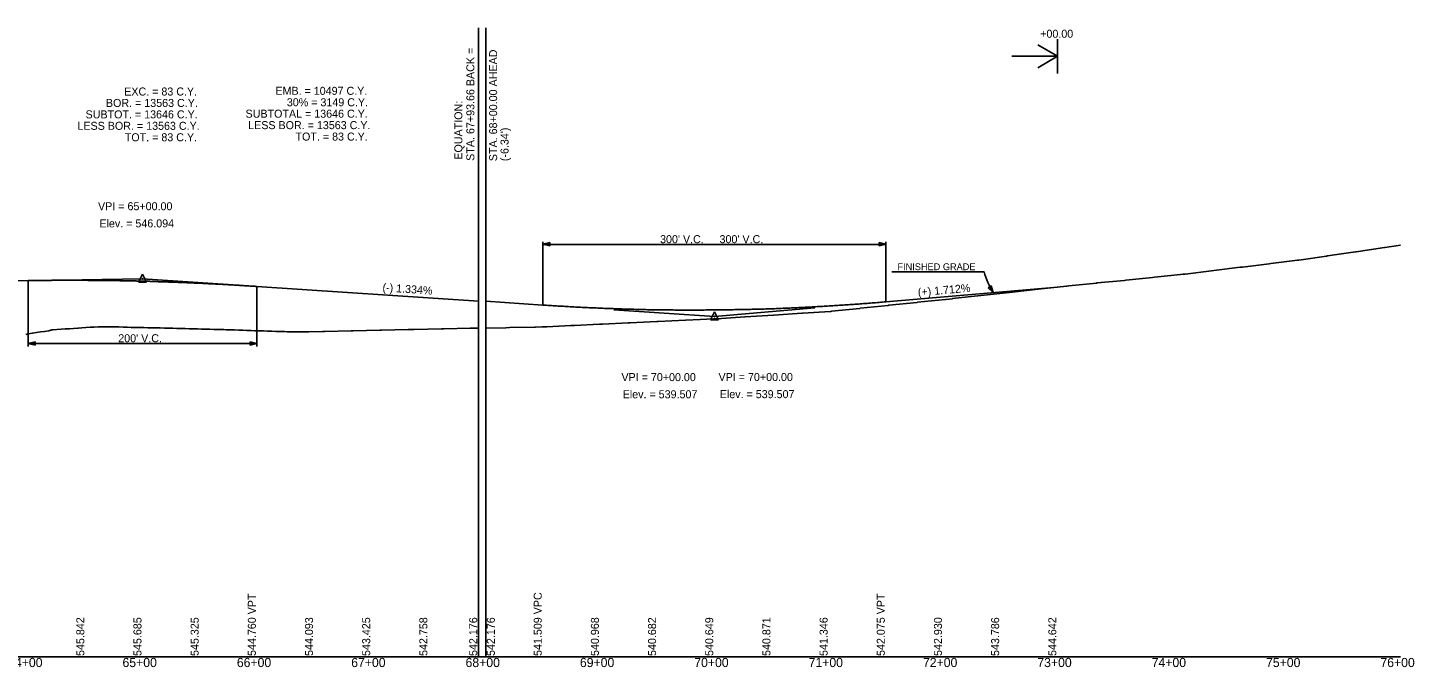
# Model space of a CAD drawing. Extents: x 1961504 to 1964196, y 1107046 to 1115093.
# Drawn here: x 1962983 to 1964196, y 1107083 to 1107643 of the extents above; entities that cross this region are included whole.
import ezdxf

# ---------------------------------------------------------------- set-up
doc = ezdxf.new("R2010")
doc.units = 0
for name, color, linetype in [('Level 40', 7, 'Continuous'), ('Level 41', 7, 'Continuous'), ('Level 42', 7, 'Continuous'), ('Level 43', 7, 'Continuous'), ('Level 45', 7, 'Continuous'), ('Level 58', 7, 'Continuous'), ('Level 63', 7, 'Continuous')]:
    doc.layers.add(name, color=color, linetype=linetype)

msp = doc.modelspace()

# ---------------------------------------------------------------- linework, layer by layer
at = {"layer": 'Level 40'}
for points in [[(1963383.7, 1107379.9), (1963401.3, 1107380.3), (1963404.6, 1107380.4), (1963426.3, 1107380.8), (1963427.3, 1107380.9), (1963433.2, 1107381), (1963437.1, 1107381.2), (1963458.2, 1107382.2), (1963461.5, 1107382.3), (1963483.2, 1107383.4), (1963485.8, 1107383.5), (1963508.3, 1107384.5), (1963510.1, 1107384.6), (1963533.3, 1107385.7), (1963534.4, 1107385.8), (1963558.3, 1107386.9), (1963558.7, 1107387), (1963571.2, 1107387.6), (1963583, 1107388.1), (1963583.4, 1107388.1), (1963585.7, 1107388.2), (1963585.7, 1107388.2), (1963610.3, 1107389.8), (1963610.7, 1107389.8), (1963635.3, 1107391.4), (1963635.7, 1107391.4), (1963660.3, 1107393), (1963660.7, 1107393), (1963685.3, 1107394.6), (1963685.7, 1107394.6), (1963686.2, 1107394.7), (1963686.2, 1107394.7), (1963710.8, 1107397.2), (1963711.2, 1107397.3), (1963735.8, 1107399.8), (1963736.2, 1107399.9), (1963760.9, 1107402.4), (1963761.2, 1107402.5), (1963785.9, 1107405), (1963786.2, 1107405.1), (1963791.8, 1107405.6), (1963791.9, 1107405.7), (1963816.6, 1107408.4), (1963816.8, 1107408.4), (1963841.7, 1107411.1), (1963841.8, 1107411.2), (1963866.7, 1107413.9), (1963866.8, 1107413.9), (1963891.7, 1107416.6), (1963891.8, 1107416.7), (1963893.5, 1107416.8), (1963893.5, 1107416.8), (1963917.8, 1107419.3), (1963918.5, 1107419.4), (1963942.2, 1107421.7), (1963943.6, 1107421.9), (1963966.7, 1107424.2), (1963968.6, 1107424.4), (1963991.2, 1107426.7), (1963993.6, 1107427), (1963995.4, 1107427.1), (1963995.5, 1107427.1), (1964018.3, 1107430), (1964020.5, 1107430.2), (1964043.6, 1107433.1), (1964045.5, 1107433.3), (1964068.9, 1107436.2), (1964070.4, 1107436.4), (1964093.7, 1107439.3), (1964094.9, 1107439.4), (1964118.9, 1107442.9), (1964119.8, 1107443.1), (1964144.2, 1107446.6), (1964144.8, 1107446.7), (1964169.6, 1107450.3), (1964169.8, 1107450.4), (1964170, 1107450.4), (1964183.7, 1107452.4)], [(1962981.5, 1107374.4), (1962983.5, 1107374.9), (1962984, 1107375), (1962987.2, 1107375.5), (1962990.8, 1107376.1), (1962994.4, 1107376.6), (1962998, 1107377.1), (1963001.6, 1107377.7), (1963002.6, 1107377.8), (1963004.4, 1107378.4), (1963005.2, 1107378.4), (1963008.8, 1107378.7), (1963012.4, 1107379), (1963016, 1107379.2), (1963019.7, 1107379.4), (1963023.3, 1107379.7), (1963026.9, 1107379.9), (1963027.7, 1107380)], [(1963027.7, 1107380), (1963030.5, 1107380.2), (1963034.1, 1107380.4), (1963037.7, 1107380.7), (1963041.3, 1107380.9), (1963044.9, 1107381.1), (1963045.7, 1107381.2), (1963048.5, 1107381.2), (1963051.5, 1107381.2), (1963052.2, 1107381.2), (1963052.9, 1107381.2), (1963053.1, 1107381.1), (1963055.8, 1107381.1), (1963056.6, 1107381.1), (1963059.4, 1107381.1), (1963059.9, 1107381.1), (1963063, 1107381), (1963066.6, 1107380.9), (1963070.2, 1107380.8), (1963073.8, 1107380.6), (1963077.4, 1107380.5), (1963081, 1107380.4), (1963081.7, 1107380.4), (1963084.7, 1107380.4), (1963088.3, 1107380.3), (1963091.9, 1107380.3), (1963091.9, 1107380.3), (1963095.5, 1107380.2), (1963099.1, 1107380.1), (1963102.7, 1107379.9), (1963106.3, 1107379.8), (1963106.7, 1107379.8), (1963108.5, 1107379.8), (1963109.9, 1107379.8), (1963110.1, 1107379.8), (1963113.6, 1107379.7), (1963117.2, 1107379.6), (1963120.8, 1107379.5), (1963124.4, 1107379.4), (1963126.1, 1107379.3), (1963128, 1107379.3), (1963131.6, 1107379.2), (1963135.2, 1107379.1), (1963135.2, 1107379.1), (1963138.8, 1107379), (1963142.4, 1107378.9), (1963146.1, 1107378.8), (1963149.7, 1107378.7), (1963153.3, 1107378.6), (1963154.7, 1107378.6), (1963156.9, 1107378.5), (1963160.2, 1107378.4), (1963160.5, 1107378.4), (1963164.1, 1107378.3), (1963167.7, 1107378.2), (1963171.3, 1107378.1), (1963174.9, 1107378), (1963178.6, 1107377.8), (1963181.8, 1107377.7), (1963182.2, 1107377.7), (1963185.2, 1107377.6), (1963185.8, 1107377.6), (1963189.4, 1107377.5), (1963193, 1107377.4), (1963196.6, 1107377.2), (1963200.2, 1107377.1), (1963203.8, 1107377), (1963207.5, 1107376.9), (1963207.7, 1107376.9), (1963210.2, 1107376.8), (1963210.6, 1107376.8), (1963211.1, 1107376.7), (1963214.7, 1107376.6), (1963216, 1107376.6), (1963218.3, 1107376.6), (1963218.4, 1107376.6), (1963221.9, 1107376.7), (1963225.5, 1107376.8), (1963229.1, 1107376.8), (1963241, 1107377.1), (1963243.1, 1107377.1), (1963266, 1107377.6), (1963267.8, 1107377.6), (1963291, 1107378.1), (1963292.6, 1107378.2), (1963316, 1107378.7), (1963316.2, 1107378.7), (1963320, 1107378.7), (1963321.3, 1107378.8), (1963345, 1107379.3), (1963347, 1107379.3), (1963370, 1107379.8), (1963372.6, 1107379.8), (1963377.3, 1107379.9)]]:
    msp.add_lwpolyline(points, dxfattribs=at)
at = {"layer": 'Level 41'}
for p, q in [((1963377.3, 1107092.6), (1963377.3, 1107642.6)), ((1963383.7, 1107092.6), (1963383.7, 1107642.6)), ((1963433.7, 1107455.4), (1963433.7, 1107400.1)), ((1963439.7, 1107454.8), (1963433.7, 1107453.3)), ((1963433.7, 1107453.3), (1963439.7, 1107451.8)), ((1963433.7, 1107452.9), (1963733.7, 1107452.9)), ((1963439.7, 1107451.8), (1963439.7, 1107454.8)), ((1963733.7, 1107453.3), (1963727.7, 1107454.8)), ((1963727.7, 1107454.8), (1963727.7, 1107451.8)), ((1963727.7, 1107451.8), (1963733.7, 1107453.3)), ((1963733.7, 1107455.4), (1963733.7, 1107402.9)), ((1963083.7, 1107427), (1963080.2, 1107420)), ((1963083.7, 1107427), (1963087.2, 1107420)), ((1963819.7, 1107429.1), (1963738.8, 1107429.1)), ((1962983.7, 1107363.9), (1962983.7, 1107421.5)), ((1962995.7, 1107421.7), (1963083.7, 1107423)), ((1963080.2, 1107420), (1963087.2, 1107420)), ((1963171.5, 1107417.2), (1963083.7, 1107423)), ((1963183.7, 1107363.9), (1963183.7, 1107416.4)), ((1963377.3, 1107403.4), (1963377.3, 1107403.4)), ((1963495.9, 1107395.9), (1963583.7, 1107390.1)), ((1963583.7, 1107394.1), (1963580.2, 1107387.1)), ((1963671.4, 1107397.6), (1963583.7, 1107390.1)), ((1963583.7, 1107394.1), (1963587.2, 1107387.1)), ((1963580.2, 1107387.1), (1963587.2, 1107387.1)), ((1962989.7, 1107367.9), (1962983.7, 1107366.4)), ((1962983.7, 1107366.4), (1962989.7, 1107364.9)), ((1962983.7, 1107366.4), (1963183.7, 1107366.4)), ((1962989.7, 1107364.9), (1962989.7, 1107367.9)), ((1963183.7, 1107366.4), (1963177.7, 1107367.9)), ((1963177.7, 1107367.9), (1963177.7, 1107364.9)), ((1963177.7, 1107364.9), (1963183.7, 1107366.4))]:
    msp.add_line(p, q, dxfattribs=at)
msp.add_lwpolyline([(1963823, 1107415.2), (1963827.4, 1107411.1), (1963825.7, 1107416.9)], close=True, dxfattribs=at)
for centre in [(1963083.7, 1107423), (1963583.7, 1107390.1)]:
    msp.add_circle(centre, 0.25, dxfattribs=at)
msp.add_arc((1963881.9, 1107445.2), 64.3, 194.4936, 212.0021, dxfattribs=at)
at = {"layer": 'Level 45'}
for p, q in [((1962383.7, 1107412.5), (1962983.7, 1107421.5)), ((1963183.7, 1107416.4), (1963377.3, 1107403.4)), ((1963733.7, 1107402.9), (1963883.7, 1107415.8)), ((1963383.7, 1107403.4), (1963433.7, 1107400.1))]:
    msp.add_line(p, q, dxfattribs=at)
for points in [[(1962983.7, 1107421.5), (1962987.7, 1107421.6), (1962991.7, 1107421.6), (1962995.7, 1107421.7), (1962999.7, 1107421.7), (1963003.7, 1107421.7), (1963007.7, 1107421.8), (1963011.7, 1107421.8), (1963015.7, 1107421.8), (1963019.7, 1107421.8), (1963023.7, 1107421.8), (1963027.7, 1107421.8), (1963031.7, 1107421.8), (1963035.7, 1107421.7), (1963039.7, 1107421.7), (1963043.7, 1107421.7), (1963047.7, 1107421.6), (1963051.7, 1107421.6), (1963055.7, 1107421.5), (1963059.7, 1107421.5), (1963063.7, 1107421.4), (1963067.7, 1107421.3), (1963071.7, 1107421.3), (1963075.7, 1107421.2), (1963079.7, 1107421.1), (1963083.7, 1107421), (1963087.7, 1107420.9), (1963091.7, 1107420.8), (1963095.7, 1107420.6), (1963099.7, 1107420.5), (1963103.7, 1107420.4), (1963107.7, 1107420.2), (1963111.7, 1107420.1), (1963115.7, 1107419.9), (1963119.7, 1107419.8), (1963123.7, 1107419.6), (1963127.7, 1107419.4), (1963131.7, 1107419.3), (1963135.7, 1107419.1), (1963139.7, 1107418.9), (1963143.7, 1107418.7), (1963147.7, 1107418.5), (1963151.7, 1107418.3), (1963155.7, 1107418.1), (1963159.7, 1107417.8), (1963163.7, 1107417.6), (1963167.7, 1107417.4), (1963171.7, 1107417.1), (1963175.7, 1107416.9), (1963179.7, 1107416.6), (1963183.7, 1107416.4)], [(1963433.7, 1107400.1), (1963439.7, 1107399.7), (1963445.7, 1107399.3), (1963451.7, 1107399), (1963457.7, 1107398.6), (1963463.7, 1107398.3), (1963469.7, 1107398), (1963475.7, 1107397.7), (1963481.7, 1107397.5), (1963487.7, 1107397.2), (1963493.7, 1107397), (1963499.7, 1107396.8), (1963505.7, 1107396.6), (1963511.7, 1107396.4), (1963517.7, 1107396.3), (1963523.7, 1107396.1), (1963529.7, 1107396), (1963535.7, 1107395.9), (1963541.7, 1107395.9), (1963547.7, 1107395.8), (1963553.7, 1107395.7), (1963559.7, 1107395.7), (1963565.7, 1107395.7), (1963571.7, 1107395.7), (1963577.7, 1107395.8), (1963583.7, 1107395.8), (1963589.7, 1107395.9), (1963595.7, 1107395.9), (1963601.7, 1107396.1), (1963607.7, 1107396.2), (1963613.7, 1107396.3), (1963619.7, 1107396.5), (1963625.7, 1107396.6), (1963631.7, 1107396.8), (1963637.7, 1107397), (1963643.7, 1107397.3), (1963649.7, 1107397.5), (1963655.7, 1107397.8), (1963661.7, 1107398.1), (1963667.7, 1107398.4), (1963673.7, 1107398.7), (1963679.7, 1107399), (1963685.7, 1107399.4), (1963691.7, 1107399.8), (1963697.7, 1107400.2), (1963703.7, 1107400.6), (1963709.7, 1107401), (1963715.7, 1107401.5), (1963721.7, 1107401.9), (1963727.7, 1107402.4), (1963733.7, 1107402.9)]]:
    msp.add_spline(points, degree=3, dxfattribs=at)
at = {"layer": 'Level 58'}
for p, q in [((1963883.7, 1107632.6), (1963883.7, 1107617.6)), ((1963883.7, 1107617.6), (1963843.7, 1107617.6)), ((1963866.4, 1107627.6), (1963883.7, 1107617.6)), ((1963866.4, 1107607.6), (1963883.7, 1107617.6)), ((1963883.7, 1107617.6), (1963883.7, 1107602.6))]:
    msp.add_line(p, q, dxfattribs=at)
at = {"layer": 'Level 63'}
msp.add_line((1961583.7, 1107092.6), (1964183.7, 1107092.6), dxfattribs=at)

# ---------------------------------------------------------------- texts
at = {"layer": 'Level 41'}
for s, height, p in [('+00.00', 7, (1963868.6, 1107633.8)), ('EXC. = 83 C.Y.', 7, (1963067.6, 1107583.3)), ('EMB. = 10497 C.Y.', 7, (1963199.8, 1107583.9)), ('SUBTOT. = 13646 C.Y.', 7, (1963033.8, 1107563.3)), ('BOR. = 13563 C.Y.', 7, (1963051.6, 1107573.3)), ('SUBTOTAL = 13646 C.Y.', 7, (1963173.7, 1107563.9)), ('30% = 3149 C.Y.', 7, (1963209.8, 1107573.9)), ('LESS BOR. = 13563 C.Y.', 7, (1963026.7, 1107553.3)), ('LESS BOR. = 13563 C.Y.', 7, (1963176, 1107553.9)), ('TOT. = 83 C.Y.', 7, (1963068.1, 1107543.3)), ('TOT. = 83 C.Y.', 7, (1963217.4, 1107543.9)), ('VPI = 65+00.00', 7, (1963044.7, 1107483)), ('Elev. = 546.094', 7, (1963045.9, 1107468)), ("300' V.C.", 7, (1963536.2, 1107454.2)), ("300' V.C.", 7, (1963588.2, 1107454.2)), ('FINISHED GRADE', 6, (1963743.8, 1107430.6)), ("200' V.C.", 7, (1963062.4, 1107367.6)), ('VPI = 70+00.00', 7, (1963502.4, 1107333.6)), ('VPI = 70+00.00', 7, (1963587.3, 1107333.7)), ('Elev. = 539.507', 7, (1963503.5, 1107318.6)), ('Elev. = 539.507', 7, (1963588.4, 1107318.7))]:
    msp.add_text(s, height=height, dxfattribs=at).set_placement(p)
for s, rotation, p in [('STA. 67+93.66 BACK =', 90, (1963373.8, 1107526.2)), ('STA. 68+00.00 AHEAD', 90, (1963393.7, 1107525.9)), ('EQUATION:', 90, (1963363.3, 1107527.2)), ("(-6.34')", 90, (1963403.7, 1107525.9)), ('(-) 1.334%', 356.1832, (1963293.3, 1107412.1)), ('(+) 1.712%', 4.8915, (1963761.9, 1107407.8))]:
    msp.add_text(s, height=7, rotation=rotation, dxfattribs=at).set_placement(p)
at = {"layer": 'Level 42'}
for s, p in [('64+00', (1962966.1, 1107083.6)), ('65+00', (1963066.1, 1107083.6)), ('66+00', (1963166.1, 1107083.6)), ('67+00', (1963266.1, 1107083.6)), ('68+00', (1963366.1, 1107083.6)), ('69+00', (1963466.1, 1107083.6)), ('70+00', (1963566.1, 1107083.6)), ('71+00', (1963666.1, 1107083.6)), ('72+00', (1963766.1, 1107083.6)), ('73+00', (1963866.1, 1107083.6)), ('74+00', (1963966.1, 1107083.6)), ('75+00', (1964066.1, 1107083.6)), ('76+00', (1964166.1, 1107083.6))]:
    msp.add_text(s, height=8, dxfattribs=at).set_placement(p)
at = {"layer": 'Level 43'}
for s, p in [('544.760 VPT', (1963182.7, 1107093.3)), ('541.509 VPC', (1963432.7, 1107093.3)), ('542.075 VPT', (1963732.7, 1107093.3)), ('545.842', (1963032.7, 1107093.3)), ('545.685', (1963082.7, 1107093.3)), ('545.325', (1963132.7, 1107093.3)), ('544.760', (1963182.7, 1107093.3)), ('544.093', (1963232.7, 1107093.3)), ('543.425', (1963282.7, 1107093.3)), ('542.758', (1963332.7, 1107093.3)), ('542.176', (1963376.3, 1107093.3)), ('542.176', (1963391.7, 1107093.3)), ('541.509', (1963432.7, 1107093.3)), ('540.968', (1963482.7, 1107093.3)), ('540.682', (1963532.7, 1107093.3)), ('540.649', (1963582.7, 1107093.3)), ('540.871', (1963632.7, 1107093.3)), ('541.346', (1963682.7, 1107093.3)), ('542.075', (1963732.7, 1107093.3)), ('542.930', (1963782.7, 1107093.3)), ('543.786', (1963832.7, 1107093.3)), ('544.642', (1963882.7, 1107093.3))]:
    msp.add_text(s, height=7, rotation=90, dxfattribs=at).set_placement(p)

doc.saveas('drawing.dxf')
